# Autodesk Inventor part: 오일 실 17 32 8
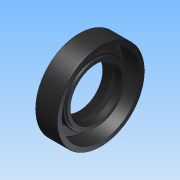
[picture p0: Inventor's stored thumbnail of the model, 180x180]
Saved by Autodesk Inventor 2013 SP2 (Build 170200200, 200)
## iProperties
Created: 2026-07
Part Number: 오일 실 17 32 8
Material: Generic
Document SubType Name: Modeling
Designer: aa
Density: 1 g/cm^3
Author: aa
변환 표준: STEP AP214IS
전처리기: Build: 200, Release: 2013 SP2 Update 6 - Date: Thu 07/17/2014
전송 단위: 밀리미터
불확실성: 0.01
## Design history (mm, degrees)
node "오일 실 17 32 81"
body "Solid1"
node "기준1"
